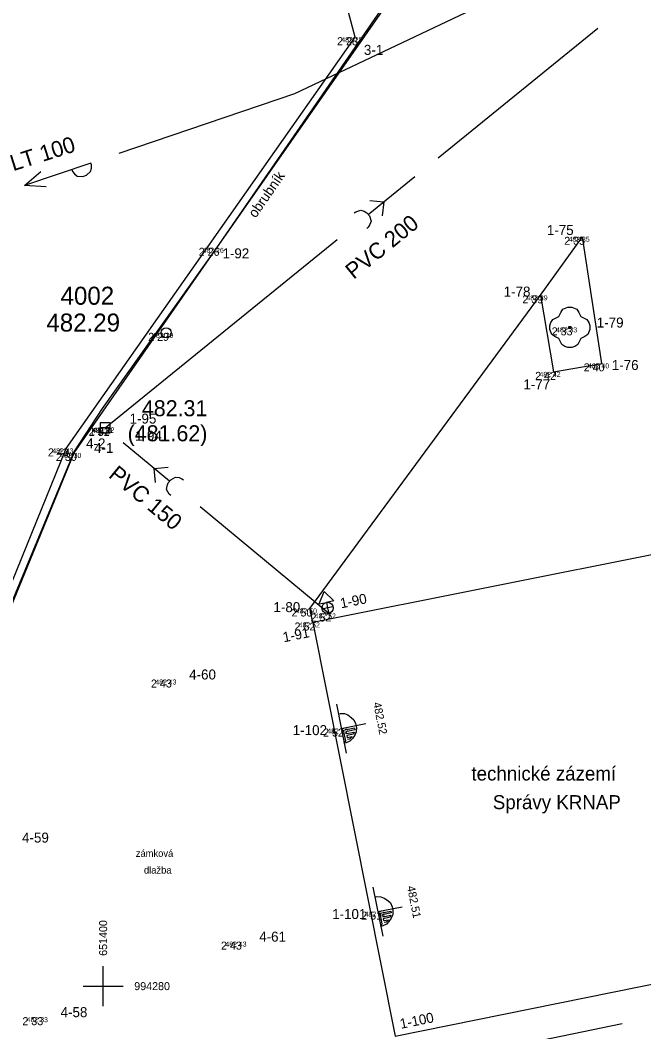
# Model space of a CAD drawing. Extents: x -651478 to -651308, y -994378 to -994071.
# Drawn here: x -651401.66 to -651389.19, y -994280.91 to -994260.69 of the extents above; entities that cross this region are included whole.
import ezdxf

# ---------------------------------------------------------------- set-up
doc = ezdxf.new("R2010")
doc.units = 0
for name, color, linetype in [('10_RAZITKO_RAMY_SEVERKA', 7, 'Continuous'), ('13_POPIS_POLOHOPISU', 7, 'Continuous'), ('18_TECKY_BODU', 7, 'Continuous'), ('19_CISLA_BODU', 7, 'Continuous'), ('20_REDUKOVANE_VYSKY_BODU', 7, 'Continuous'), ('22_JEDNOTL_STROMY', 7, 'Continuous'), ('25_CHODNIKY', 7, 'Continuous'), ('34_KANAL-VEDENI', 7, 'Continuous'), ('35_KANAL-OBEKTY', 7, 'Continuous'), ('38_VODA-VEDENI', 7, 'Continuous'), ('52_UPLNE_VYSKY_NADZEMNICH_ZNAKU', 7, 'Continuous'), ('61_UPLNE_VYSKY_BODU', 7, 'Continuous'), ('63_VOLNA_V', 7, 'Continuous'), ('_KM', 7, 'Continuous'), ('ROZP', 7, 'Continuous'), ('rybnik oprava', 7, 'Continuous')]:
    doc.layers.add(name, color=color, linetype=linetype)

# ---------------------------------------------------------------- blocks, each defined once
blk = doc.blocks.new('POINT_DISPLAY')
blk.add_line((0, 0), (0, 0))
blk = doc.blocks.new('Z24')
for p, q in [((-0.34, 0.16), (-0.22, 0.22)), ((-0.22, 0.22), (-0.18, 0.3)), ((-0.18, 0.3), (-0.14, 0.36)), ((-0.14, 0.36), (-0.04, 0.4)), ((-0.04, 0.4), (0.04, 0.4)), ((0.04, 0.4), (0.14, 0.36)), ((0.14, 0.36), (0.18, 0.3)), ((0.18, 0.3), (0.22, 0.22)), ((0.22, 0.22), (0.34, 0.16)), ((-0.4, 0.04), (-0.38, 0.1)), ((-0.4, -0.04), (-0.4, 0.04)), ((-0.38, 0.1), (-0.34, 0.16)), ((-0.02, -0.02), (-0.02, 0.02)), ((-0.02, 0.02), (0.02, 0.02)), ((0.02, 0.02), (0.02, -0.02)), ((0.34, 0.16), (0.38, 0.1)), ((0.38, 0.1), (0.4, 0.04)), ((0.4, 0.04), (0.4, -0.04)), ((-0.36, -0.14), (-0.4, -0.04)), ((-0.3, -0.18), (-0.36, -0.14)), ((-0.22, -0.22), (-0.3, -0.18)), ((0.02, -0.02), (-0.02, -0.02)), ((0.3, -0.18), (0.22, -0.22)), ((0.36, -0.14), (0.3, -0.18)), ((0.4, -0.04), (0.36, -0.14)), ((-0.16, -0.34), (-0.22, -0.22)), ((-0.1, -0.38), (-0.16, -0.34)), ((-0.04, -0.4), (-0.1, -0.38)), ((0.04, -0.4), (-0.04, -0.4)), ((0.1, -0.38), (0.04, -0.4)), ((0.16, -0.34), (0.1, -0.38)), ((0.22, -0.22), (0.16, -0.34))]:
    blk.add_line(p, q)
blk = doc.blocks.new('Z46260')
for p, q in [((0.1, 0.1), (-0.1, 0.1)), ((-0.1, 0.1), (-0.1, -0.1)), ((0.1, 0), (-0.1, 0)), ((0.1, -0.1), (0.1, 0.1)), ((-0.1, -0.1), (0.1, -0.1))]:
    blk.add_line(p, q)
blk = doc.blocks.new('Z105')
for radius in [0.1, 0.002]:
    blk.add_circle((0, 0), radius)
blk = doc.blocks.new('Z916')
for p, q in [((0, 0), (0, 0.5)), ((-0.24, 0.18), (-0.18, 0.24)), ((-0.18, 0.24), (-0.12, 0.28)), ((-0.12, 0.28), (-0.04, 0.3)), ((-0.04, 0.3), (0.04, 0.3)), ((0.04, 0.3), (0.12, 0.28)), ((0.04, 0.04), (0.04, 0.26)), ((0.04, 0.26), (0.08, 0.26)), ((0.08, 0.26), (0.08, 0.08)), ((0.12, 0.28), (0.18, 0.24)), ((0.12, 0.08), (0.12, 0.24)), ((0.12, 0.24), (0.16, 0.22)), ((0.16, 0.22), (0.16, 0.08)), ((0.18, 0.24), (0.24, 0.18)), ((-0.5, 0), (0.5, 0)), ((-0.3, 0.04), (-0.28, 0.12)), ((-0.3, 0), (-0.3, 0.04)), ((-0.28, 0.12), (-0.24, 0.18)), ((0.26, 0.04), (0.04, 0.04)), ((0.08, 0.08), (0.12, 0.08)), ((0.16, 0.08), (0.2, 0.08)), ((0.2, 0.08), (0.2, 0.18)), ((0.2, 0.18), (0.24, 0.12)), ((0.24, 0.18), (0.28, 0.12)), ((0.24, 0.12), (0.24, 0.08)), ((0.3, 0), (0.26, 0.04)), ((0.28, 0.12), (0.3, 0.04)), ((0.3, 0.04), (0.3, 0))]:
    blk.add_line(p, q)
blk = doc.blocks.new('Z626')
for p, q in [((-0.7, 0.2), (-0.66, 0.2)), ((-0.66, 0.2), (-0.56, 0.16)), ((-0.56, 0.16), (-0.52, 0.1)), ((-0.52, 0.1), (-0.5, 0.04)), ((-0.5, 0.04), (-0.5, -0.04)), ((-0.5, 0), (0.7, 0)), ((-0.3, 0.2), (-0.1, 0)), ((-0.1, 0), (-0.3, -0.2)), ((-0.66, -0.2), (-0.7, -0.2)), ((-0.6, -0.18), (-0.66, -0.2)), ((-0.54, -0.14), (-0.6, -0.18)), ((-0.5, -0.04), (-0.54, -0.14))]:
    blk.add_line(p, q)
blk = doc.blocks.new('Z70')
for p, q in [((0, -0.4), (0, 0.4)), ((-0.4, 0), (0.4, 0))]:
    blk.add_line(p, q)
blk = doc.blocks.new('Z616')
for p, q in [((-0.68, 0.1), (-0.7, 0.04)), ((-0.7, 0.04), (-0.7, 0)), ((-0.7, 0), (0.7, 0)), ((-0.64, 0.16), (-0.68, 0.1)), ((-0.54, 0.2), (-0.64, 0.16)), ((-0.46, 0.2), (-0.54, 0.2)), ((-0.36, 0.16), (-0.46, 0.2)), ((-0.32, 0.1), (-0.36, 0.16)), ((-0.3, 0.04), (-0.32, 0.1)), ((-0.3, 0), (-0.3, 0.04)), ((0.3, 0.16), (0.7, 0)), ((0.7, 0), (0.3, -0.16))]:
    blk.add_line(p, q)

msp = doc.modelspace()

# ---------------------------------------------------------------- linework, layer by layer
at = {"layer": '25_CHODNIKY'}
for p, q in [((-651397.73, -994265.24), (-651394.32, -994260.31)), ((-651394.96, -994261.03), (-651395.12, -994260.43)), ((-651400.74, -994269.25), (-651394.96, -994261.03)), ((-651391.26, -994266.19), (-651390.42, -994265.02)), ((-651390.03, -994267.55), (-651390.42, -994265.02)), ((-651400.58, -994269.34), (-651397.73, -994265.24)), ((-651391.26, -994266.19), (-651391, -994267.72)), ((-651391, -994267.72), (-651390.03, -994267.55)), ((-651402.62, -994273.88), (-651400.74, -994269.25)), ((-651402.47, -994273.94), (-651400.58, -994269.34))]:
    msp.add_line(p, q, dxfattribs=at)
at = {"layer": '34_KANAL-VEDENI'}
for p, q in [((-651393.304, -994263.439), (-651390.112, -994260.849)), ((-651399.96, -994268.84), (-651395.323, -994265.077)), ((-651395.49, -994272.55), (-651398.058, -994270.418)), ((-651389.625, -994280.75), (-651393.522, -994281.556))]:
    msp.add_line(p, q, dxfattribs=at)
at = {"layer": '35_KANAL-OBEKTY'}
for p, q in [((-651395.681, -994272.358), (-651395.579, -994272.108)), ((-651395.579, -994272.108), (-651395.387, -994272.299)), ((-651395.681, -994272.358), (-651395.534, -994272.328)), ((-651395.387, -994272.299), (-651395.534, -994272.328)), ((-651395.534, -994272.328), (-651395.512, -994272.439)), ((-651395.512, -994272.439), (-651395.623, -994272.461)), ((-651395.401, -994272.417), (-651395.512, -994272.439)), ((-651395.512, -994272.439), (-651395.49, -994272.55))]:
    msp.add_line(p, q, dxfattribs=at)
msp.add_circle((-651395.512, -994272.439), 0.113, dxfattribs=at)
at = {"layer": '38_VODA-VEDENI'}
for p, q in [((-651396.169, -994262.153), (-651390.168, -994259.308)), ((-651399.678, -994263.351), (-651396.169, -994262.153))]:
    msp.add_line(p, q, dxfattribs=at)
at = {"layer": '63_VOLNA_V'}
for p, q in [((-651395.87, -994272.45), (-651391.26, -994266.19)), ((-651395.81, -994272.73), (-651395.87, -994272.45))]:
    msp.add_line(p, q, dxfattribs=at)
at = {"layer": '_KM'}
for p, q in [((-651397.73, -994265.24), (-651391.47, -994256.28)), ((-651400.01, -994268.45), (-651397.73, -994265.24)), ((-651400.58, -994269.32), (-651400.01, -994268.45)), ((-651402.95, -994275.01), (-651400.58, -994269.32))]:
    msp.add_line(p, q, dxfattribs=at)
at = {"layer": 'rybnik oprava'}
for p, q in [((-651383.287, -994270.233), (-651395.81, -994272.73)), ((-651395.81, -994272.73), (-651394.16, -994281)), ((-651394.16, -994281), (-651368.14, -994275.72))]:
    msp.add_line(p, q, dxfattribs=at)

# ---------------------------------------------------------------- block references
at = {"layer": '10_RAZITKO_RAMY_SEVERKA', "rotation": -75.84660000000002}
msp.add_blockref('Z105', (-651398.74, -994266.94), dxfattribs=at)
at = {"layer": '13_POPIS_POLOHOPISU', "rotation": -78.71670000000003}
for p in [(-651395.24, -994274.85), (-651394.51, -994278.51)]:
    msp.add_blockref('Z916', p, dxfattribs=at)
at = {"layer": '18_TECKY_BODU'}
for p in [(-651394.96, -994261.03), (-651390.42, -994265.02), (-651397.73, -994265.24), (-651391.26, -994266.19), (-651390.67, -994266.83), (-651398.74, -994266.94), (-651391, -994267.72), (-651390.03, -994267.55), (-651399.96, -994268.84), (-651399.93, -994268.83), (-651400.74, -994269.25), (-651400.58, -994269.34), (-651395.87, -994272.45), (-651395.49, -994272.55), (-651395.81, -994272.73), (-651398.68, -994273.87), (-651395.24, -994274.85), (-651394.51, -994278.51), (-651397.28, -994279.11), (-651401.25, -994280.62)]:
    msp.add_blockref('POINT_DISPLAY', p, dxfattribs=at)
at = {"layer": '22_JEDNOTL_STROMY'}
msp.add_blockref('Z24', (-651390.67, -994266.83), dxfattribs=at)
at = {"layer": '34_KANAL-VEDENI'}
for p, rotation in [((-651394.313, -994264.258), 39.0565), ((-651399.059, -994269.588), 140.3081)]:
    msp.add_blockref('Z626', p, dxfattribs=dict(at, rotation=rotation))
at = {"layer": '35_KANAL-OBEKTY'}
msp.add_blockref('Z46260', (-651399.96, -994268.84), dxfattribs=at)
at = {"layer": '38_VODA-VEDENI', "rotation": -161.14990000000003}
msp.add_blockref('Z616', (-651400.908, -994263.771), dxfattribs=at)
at = {"layer": 'ROZP'}
msp.add_blockref('Z70', (-651400, -994280), dxfattribs=at)

# ---------------------------------------------------------------- texts
at = {"layer": '10_RAZITKO_RAMY_SEVERKA'}
for s, p in [('4002', (-651400.85, -994266.378)), ('482.29', (-651401.134, -994266.914))]:
    msp.add_text(s, height=0.36, dxfattribs=at).set_placement(p)
at = {"layer": '13_POPIS_POLOHOPISU'}
msp.add_text('obrubník', height=0.2, rotation=55.329, dxfattribs=at).set_placement((-651396.95, -994264.657))
for s, height, p in [('technické zázemí', 0.28, (-651392.638, -994275.889)), ('Správy KRNAP', 0.28, (-651392.211, -994276.462)), ('zámková', 0.14, (-651399.347, -994277.415)), ('dlažba', 0.14, (-651399.184, -994277.749))]:
    msp.add_text(s, height=height, dxfattribs=at).set_placement(p)
at = {"layer": '19_CISLA_BODU'}
for s, p in [('3-1', (-651394.787, -994261.383)), ('1-75', (-651391.13, -994264.985)), ('1-92', (-651397.614, -994265.451)), ('1-78', (-651391.994, -994266.216)), ('1-79', (-651390.132, -994266.834)), ('1-76', (-651389.832, -994267.683)), ('1-77', (-651391.599, -994268.069)), ('1-95', (-651399.471, -994268.754)), ('1-94', (-651399.361, -994269.095)), ('4-2', (-651400.34, -994269.25)), ('4-1', (-651400.18, -994269.34)), ('1-80', (-651396.595, -994272.523)), ('4-60', (-651398.28, -994273.87)), ('1-102', (-651396.209, -994274.982)), ('4-59', (-651401.62, -994277.13)), ('1-101', (-651395.422, -994278.658)), ('4-61', (-651396.88, -994279.11)), ('4-58', (-651400.85, -994280.62))]:
    msp.add_text(s, height=0.2, dxfattribs=at).set_placement(p)
for s, rotation, p in [('1-90', 11.2746, (-651395.241, -994272.448)), ('1-91', 11.2746, (-651396.387, -994273.126)), ('1-100', 11.4708, (-651394.047, -994280.854))]:
    msp.add_text(s, height=0.2, rotation=rotation, dxfattribs=at).set_placement(p)
at = {"layer": '20_REDUKOVANE_VYSKY_BODU'}
for s, p in [(' 2 28', (-651395.383, -994261.19)), (' 2 35', (-651390.843, -994265.18)), (' 2 26', (-651398.149, -994265.4)), (' 2 39', (-651391.679, -994266.35)), (' 2 33', (-651391.093, -994266.99)), (' 2 29', (-651399.159, -994267.1)), (' 2 42', (-651391.423, -994267.88)), (' 2 40', (-651390.453, -994267.71)), (' 2 31', (-651400.349, -994269)), (' 1 62', (-651400.338, -994268.99)), (' 2 43', (-651401.163, -994269.41)), (' 2 30', (-651401.003, -994269.5)), (' 2 50', (-651396.293, -994272.61)), (' 2 52', (-651395.913, -994272.71)), (' 2 52', (-651396.233, -994272.89)), (' 2 43', (-651399.103, -994274.03)), (' 2 52', (-651395.663, -994275.01)), (' 2 51', (-651394.899, -994278.67)), (' 2 43', (-651397.703, -994279.27)), (' 2 33', (-651401.673, -994280.78))]:
    msp.add_text(s, height=0.16, dxfattribs=at).set_placement(p)
at = {"layer": '34_KANAL-VEDENI'}
for s, rotation, p in [('PVC 200', 39.0565, (-651394.993, -994265.882)), ('PVC 150', 320.3081, (-651399.91, -994269.813))]:
    msp.add_text(s, height=0.32, rotation=rotation, dxfattribs=at).set_placement(p)
at = {"layer": '38_VODA-VEDENI'}
msp.add_text('LT 100', height=0.32, rotation=17.568, dxfattribs=at).set_placement((-651401.798, -994263.71))
at = {"layer": '52_UPLNE_VYSKY_NADZEMNICH_ZNAKU'}
for s, p in [('482.31', (-651399.225, -994268.607)), ('(481.62)', (-651399.51, -994269.108))]:
    msp.add_text(s, height=0.32, dxfattribs=at).set_placement(p)
for s, p in [('482.52', (-651394.603, -994274.34)), ('482.51', (-651393.927, -994278.011))]:
    msp.add_text(s, height=0.16, rotation=281.2833, dxfattribs=at).set_placement(p)
at = {"layer": '61_UPLNE_VYSKY_BODU'}
for s, p in [('482 28 ', (-651395.239, -994261.13)), ('482 35 ', (-651390.697, -994265.12)), ('482 26 ', (-651398.01, -994265.34)), ('482 39 ', (-651391.538, -994266.29)), ('482 33 ', (-651390.946, -994266.93)), ('482 29 ', (-651399.02, -994267.04)), ('482 42 ', (-651391.278, -994267.82)), ('482 40 ', (-651390.307, -994267.65)), ('482 31 ', (-651400.223, -994268.94)), ('481 62 ', (-651400.195, -994268.93)), ('482 43 ', (-651401.016, -994269.35)), ('482 30 ', (-651400.857, -994269.44)), ('482 50 ', (-651396.148, -994272.55)), ('482 52 ', (-651395.769, -994272.65)), ('482 52 ', (-651396.089, -994272.83)), ('482 43 ', (-651398.956, -994273.97)), ('482 52 ', (-651395.519, -994274.95)), ('482 51 ', (-651394.774, -994278.61)), ('482 43 ', (-651397.556, -994279.21)), ('482 33 ', (-651401.526, -994280.72))]:
    msp.add_text(s, height=0.1, dxfattribs=at).set_placement(p)
at = {"layer": 'ROZP'}
msp.add_text('651400', height=0.16, rotation=90, dxfattribs=at).set_placement((-651399.92, -994279.394))
msp.add_text('994280', height=0.16, dxfattribs=at).set_placement((-651399.378, -994280.08))

doc.saveas('drawing.dxf')
